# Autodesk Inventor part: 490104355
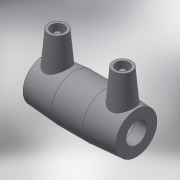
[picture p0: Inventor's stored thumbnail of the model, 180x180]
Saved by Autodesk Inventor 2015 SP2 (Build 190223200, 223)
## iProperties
Created: 2017-06
Part Number: 490104355
Material: Generic
Description: PLASSON COUPLER 355-355
Document SubType Name: Modeling
Designer: KIM
Mass: 55.0731 g
Surface Area: 148.067 cm^2
Volume: 55.0731 cm^3
Density: 1 g/cm^3
Appearance: Default
Author: KIM
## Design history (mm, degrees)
derived "490104.ipt"
feature "Solid1::490104.ipt"
tag "TaggingFeature1"
body "Solid1"
other parameters: "d0" = 277, "d1" = 355, "d2" = 431, "d3" = 137, "d4" = 92.33333, "d5" = 387.9, "d6" = 337.25, "d7" = 355, "d8" = 168 deg, "d10" = 54.8, "d11" = 18.26667, "d13" = 277, "d14" = 17.6296, "d15" = 137, "d16" = 137, "d17" = 337.25, "d18" = 355, "d19" = 3.52592, "d20" = 168 deg, "d22" = 405.14, "d23" = 431, "d24" = 392.9858, "d25" = 135 deg, "d26" = 152.35, "d27" = 135 deg, "d29" = 203, "d30" = 14, "d31" = 96.95, "d34" = 5 deg, "d35" = 15, "d39" = 5 deg, "d41" = 4, "d42" = 14, "d43" = 0, "d45" = 4, "d46" = 14, "d47" = 0, "d48" = 3, "d49" = 0, "d50" = 3, "d51" = 0, "d52" = 39.73, "d53" = 9.9325, "d_" = 355, "L_" = 277, "L_1" = 137, "D_" = 431, "A_" = 203, "d_2" = 12
